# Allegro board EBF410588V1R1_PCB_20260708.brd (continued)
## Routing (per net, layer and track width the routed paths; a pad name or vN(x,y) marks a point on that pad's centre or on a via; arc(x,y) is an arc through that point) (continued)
VBUS5V0_TYPEC: length 36.8
  TOP w0.254: v1(26.56,81.61) J10.A9 ; v1(26.36,86.39) 26.8,85.96 J10.B4 ; J10.A4 29.06,81.73 v1(29.16,81.64) ; v1(29.8,86.39) 29.3,85.89 J10.B9
  TOP w0.305: v1(41.12,66.5) 42.88,68.25 42.88,69.14 42.24,69.77 42.24,83.64 v1(41.25,84.63)
  TOP w0.381: v1(26.57,80.75) 26.56,80.75 v1(26.56,81.61) ; v1(29.8,86.39) v1(29.8,87.39) ; v1(26.36,86.39) v1(26.36,87.39) ; v1(29.16,81.64) v1(29.74,81.05)
  BOTTOM w0.254: U11.2 40.97,66.34 v1(41.12,66.5)
  BOTTOM w0.508: 26.64,81.54 26.64,80.82 v1(26.57,80.75) 26.57,80.47 26.79,80.25 C103.1 ; 26.64,81.54 v1(26.56,81.61) ; 26.64,81.54 26.74,81.43 28.96,81.43 v1(29.16,81.64) v1(29.74,81.05)
VCC3V3_RTC_S5: length 24
  BOTTOM w0.254: R241.1 21.97,46.35 24.18,44.15 32.87,44.15 U6.2
  BOTTOM w0.381: D9.2 38.02,49.5 38.02,48.44 37.47,47.89 C31.1 36.89,47.43 U6.2
VCC5V0_SYS_S5: length 203.9
  ART04 w0.254: v1(3.38,50.11) 3.35,50.11 2.46,49.22 2.46,46.23 2.82,45.87 2.82,9.17 3.35,8.64 7.65,8.64 8.15,8.13 8.15,1.83 8.66,1.32 118.8,1.32 119.1,1.02 135.46,1.02 136.22,1.78 136.91,1.78 v1(137.53,2.4)
  BOTTOM w0.254: v1(60.05,39.42) 60.05,39.66 R198.2 ; R6.2 C11.2 12.62,60.71 13.13,60.2 13.13,55.65 12.01,54.53 ; R4.1 v1(137.53,2.4) ; v1(3.38,50.11) 4.27,51 9.96,51 11.67,52.71 v1(11.67,52.72)
  vias: v1(11.67,53.72) v1(12.67,53.72) v1(12.67,52.72) v1(13.67,53.72) v1(13.67,52.72) v1(34.52,47.37) v1(51.12,17.51) v1(51.12,16.51) v1(52.12,17.51) v1(52.12,16.51) v1(53.12,17.51) v1(53.12,16.51)
VCC5V0_USB20_HOST: length 16.7
  ART04 w0.508: J11.10 120.19,77.18 ; J11.10 119.46,77.91 ; J11.10 118.73,77.18 ; J11.10 119.46,76.45 ; J12.7 138.33,78.5 ; J12.7 137.36,79.48 ; J12.7 136.38,78.5 ; J12.7 137.36,77.52
  BOTTOM w1.016: 137.57,85.29 137.57,78.71 J12.7 J12.1
VCC5V0_USB30_HOST: length 5.1
  BOTTOM w0.762: J11.1 119.46,85.44
VCC_1V8_S3: length 124.6
  TOP w0.254: 37.71,49.67 v1(30.87,49.67) 29.68,49.67 28.35,48.34 v1(25.83,48.34)
  TOP w0.381: v1(39.67,48.83) 38.55,48.83 37.71,49.67 37.73,49.67 38.25,50.19 38.25,54.25 39.56,55.56 v1(42.59,55.56)
  ART03 w0.381: v1(42.59,55.56) 42.72,55.69 42.72,59 41.99,59.74 41.99,66.45 42.57,67.03 44.07,67.03 44.48,67.44 45.9,67.44 47.99,65.34 53.24,65.34 v1(53.69,64.9) 54.51,65.72 54.51,66.67 56.11,68.28 69.93,68.28 72.14,66.07 72.14,64.2 v1(72.31,64.02)
  BOTTOM w0.254: R159.1 76.19,63 74.55,64.64 72.93,64.64 v1(72.31,64.02) ; v1(53.69,64.9) 53.94,64.64 56.02,64.64 R158.1 ; v1(25.83,48.34) 26.38,48.89 R156.1
  BOTTOM w0.508: D58.2 59.09,8.73 59.82,8 64.39,8 65,7.39 65,5.28 65.43,4.85 65.43,2.69 65.94,2.18 80.26,2.18 80.77,2.69 92.7,2.69 J30.1
  vias: v1(56.47,13.87) v1(56.47,12.87)
VCC_3V3_S0: length 105.1
  ART03 w0.508: v1(128.1,17.7) 126.47,16.07 126.47,13.92 125.6,13.06 113.84,13.06 109.8,9.02 109.8,7.01 108.61,5.82 98.63,5.82 94.26,1.45 62.53,1.45 61.37,2.62 61.37,6.5 58.32,9.55 58.32,10.77 57.23,11.86 53.61,11.86 53.1,12.37 53.1,15.49 v1(54.12,16.51) v1(54.12,17.51)
  BOTTOM w0.305: J4.4 132.49,18.51 C21.1 132.45,18.48 131.88,17.91 130.42,17.91 C20.1 129.79,18.48 129.24,17.93 128.33,17.93 v1(128.1,17.7)
  vias: v1(55.12,17.51) v1(55.12,16.51)
VCC_RTC: length 14.6
  BOTTOM w0.254: D9.3 34.12,53.45 33.66,53.92 30.23,53.92 29.49,53.18 29.49,50.3 29.84,49.94 R157.1 R32.1
  BOTTOM w0.305: C26.1 32.42,51.35 U5.8
  BOTTOM w0.381: D9.3 33.5,52.32 33,51.82 C26.1
VCCA1V8_PLDO2_S0: length 19.7
  TOP w0.254: CN4.21 56.32,15.79 56.12,15.99 v1(56.12,16.51)
  BOTTOM w0.254: v1(39.67,49.83) 40.52,50.67 42.55,50.67 44.55,52.68 55.1,52.68 R15.1
VDD_3V3: length 285.6
  TOP w0.203: U7.28 61.91,59.86 62.1,59.66 62.31,59.87 U7.29 ; U8.28 80.32,59.84 80.51,59.65 80.72,59.87 U8.29
  TOP w0.254: R82.2 R91.1 L9.1 v1(44.74,68.95) ; v1(49.17,69.8) 49.47,69.8 R87.1 ; U28.5 v1(3.44,78.48) ; C33.1 64.02,58.31 63.09,59.23 62.33,59.23 62.1,59.46 62.1,59.66 ; R21.1 v1(140.59,6.78) ; v1(35.56,83.54) 36.25,82.85 36.25,70.33 35.88,69.97 v1(35.88,68.33) ; v1(78.23,54.13) R58.1 R57.1 ; U29.5 v1(7.31,68.09) ; R142.1 v1(100.76,54.86) ; R35.1 57.78,54.1 58.29,53.59 59.31,53.59 59.82,54.1 R34.1 R33.1 v1(60.83,54.13) ; v1(71.25,22.86) 71.25,20.22 v1(74.4,17.07) v1(74.4,15.95) 74.4,13.87 v1(74.37,13.84) ; R141.1 v1(104.19,54.86) ; 80.51,59.65 80.51,59.42 80.7,59.23 81.49,59.23 C51.1
  TOP w0.305: v1(81.28,54.13) R59.1 81.36,54.87 82.37,55.88 C49.1 C50.1 C51.1
  TOP w0.381: v1(12.7,16.1) C196.1 14.04,16.9 14.35,16.59 U35.5 ; R22.1 v1(135.53,8.5) ; L16.1 v1(38.35,10.63) ; U34.5 21.72,16.59 21.4,16.9 C189.1 v1(19.94,16.1) ; L15.2 12.99,32.03 v1(13.44,32.03) ; v1(35.88,68.33) 36.39,67.82 40.44,67.82 v1(41.12,68.5) ; R127.1 v1(131.32,54.15)
  TOP w0.508: C34.1 v1(64.02,56.58) C35.1 C33.1 ; v1(54.9,60.97) 54.77,60.84 L8.1
  ART03 w0.254: v1(7.31,68.09) 7.31,65.71 7.82,65.2 16.28,65.2 v1(16.81,65.74) ; v1(100.76,54.86) v1(104.19,54.86) 106.45,54.86 108.31,56.73 v1(108.31,66.79)
  ART03 w0.508: v1(19.94,16.1) 19.43,15.6 15.24,15.6 14.73,16.1 v1(12.7,16.1)
  ART04 w0.254: v1(84.26,60.58) 86.26,60.58 87.05,61.37 89.28,61.37
  ART04 w0.508: 29.87,30.2 30.42,30.75 v1(30.91,30.75) ; 144.73,43.01 J32.17 ; J32.17 143.75,43.99 ; J32.17 144.73,44.97
  BOTTOM w0.254: v1(16.81,65.74) 17.26,65.29 R3.1 ; R145.1 137.45,6.88 140.49,6.88 v1(140.59,6.78) 140.96,6.41 R144.1 ; U11.13 39.19,68.02 38.94,68.28 ; v1(3.44,78.48) 3.44,78.49 C176.1 5.34,77.46 6.34,76.46 C177.1 7.04,67.82 v1(7.31,68.09) ; 38.94,68.28 38.94,68.55 38.73,68.76 37.08,68.76 36.83,68.5 36.83,67.82 36.58,67.56 C91.1 ; 38.94,68.28 38.69,68.03 U11.12 ; L5.1 v1(57.42,68.87) ; v1(74.37,13.84) R160.1 R162.1 ; R109.1 41.92,66.4 C92.1 41.34,65.84 U11.3 ; R189.1 96.16,18.16 96.75,17.58 102.95,17.58 105.16,15.36 v1(105.16,11.12) ; R189.1 R190.1 ; R189.1 96.13,18.15 95.5,17.53 94.11,17.53 93.6,17.02 93.6,13.59 94.1,13.09 R163.1 R188.1 ; R77.1 77.21,62.99 R72.1 R71.1 78.22,59.95 R70.1 83.63,59.95 v1(84.26,60.58) 85.5,60.58 85.95,61.04 85.95,61.96 R150.1 ; R236.1 v1(74.4,17.07) ; v1(30.91,30.75) 30.17,31.49 30.17,32.43 30.53,32.79 32.44,32.79 36.65,37.01 49.08,37.01 R240.1 R239.1 ; R238.1 R237.1 71.64,23.25 v1(71.25,22.86) ; v1(81.28,54.13) 81.42,54.26 R103.1 ; v1(107.31,66.79) 106.56,66.03 R146.1 104.19,64.81 Q7.1 ; R97.2 v1(35.56,83.54) ; R235.1 v1(74.4,15.95) ; R12.1 v1(140.96,2.64) ; v1(89.59,65.13) 89.9,64.81 Q6.1 90.61,64.2 90.32,63.91 89.64,63.91 89.38,63.65 89.38,63.1 R139.1 ; v1(65.85,60.58) 65.22,59.95 R46.1 59.67,59.95 R47.1 R48.1 58.67,61.98 R53.1 ; U25.5 v1(124.14,16.65)
  BOTTOM w0.305: R136.1 81.41,47.23 v1(81.37,47.27) ; L7.1 v1(75.83,68.87)
  BOTTOM w0.381: v1(32.51,9.63) 32.53,9.63 33.53,10.63 L17.1 ; v1(44.74,68.95) 44.86,68.83 44.86,67.13 44.35,66.62 44.35,65 44.09,64.74 43.37,64.74 42.92,65.18 R109.1 ; C91.1 v1(35.88,68.33) 35.88,69.07 35.43,69.52 33.6,69.52 32.49,70.64 18.11,70.64 17.4,69.93 17.4,66.32 v1(16.81,65.74)
  vias: v1(53.9,10.18) v1(53.9,9.18) v1(54.9,10.18) v1(54.9,9.18) v1(68.55,8.97) v1(69.6,8.97) v1(70.6,8.97) v1(70.6,7.97) v1(107.31,67.79) v1(108.31,67.79) v1(114.92,42.27) v1(115.92,42.27) v1(123.14,17.65) v1(123.14,16.65) v1(129.32,68.04) v1(129.32,67.04) v1(130.32,68.04) v1(130.32,67.04)
VDD_5V: length 39.8
  TOP w0.254: C153.1 11.13,29.72 v1(11.14,29.71) ; R10.1 49.5,54.51 v1(49.96,54.51) ; Q1.2 49.59,55.68 v1(49.96,55.31) ; R126.1 v1(129.29,57.59) ; C151.1 11.13,13.84 v1(11.14,13.84)
  TOP w0.381: U34.3 22.99,21.84 C190.1 v1(22.33,21.97) ; v1(14.96,21.97) C197.1 15.62,21.84 U35.3
  ART04 w0.508: J32.4 148.25,61.77 ; J32.4 147.27,60.79 ; J32.4 147.27,62.75 ; J32.4 146.29,61.77 ; 146.29,64.31 J32.2 ; J32.2 147.27,65.29 ; J32.2 148.25,64.31 ; J32.2 147.27,63.33
  BOTTOM w0.254: R147.1 100.97,65.54 103.27,65.54 v1(103.54,65.82) ; C8.1 17.26,55.06 19.1,56.9 19.1,61.21 18.59,61.72 C2.2 R1.2 ; R140.1 91.32,65.66 88.16,65.66 Q10.1 ; C155.1 v1(11.13,25.78) ; U24.5 v1(117.54,16.65)
  vias: v1(9.93,47.09) v1(10.74,47.09) v1(11.14,30.71) v1(11.13,24.78) v1(11.14,12.84) v1(17.67,53.72) v1(17.67,52.72) v1(18.67,53.72) v1(18.67,52.72) v1(19.67,53.72) v1(19.67,52.72) v1(27.97,59.64) v1(27.97,58.64) v1(33.66,79.12) v1(33.66,78.12) v1(34.65,79.12) v1(34.65,78.12) v1(73.24,8.97) v1(74.3,8.97) v1(75.29,8.97) v1(75.29,7.97) v1(94.31,66.3) v1(94.31,65.3) v1(116.3,88.1) v1(116.3,87.1) v1(116.54,17.65) v1(116.54,16.65) v1(117.53,87.1) v1(132.68,88.1) v1(132.68,87.1) v1(133.91,87.1)
BAT_RTC: length 6.9
  BOTTOM w0.381: D9.1 36.89,53.28 C24.1 38.01,53.5 D10.2 38.73,54.86 39.49,55.62 J5.1
BM8563_INT: length 9.9
  BOTTOM w0.152: R157.2 R32.2 28.83,47.95 D18.1 ; Q3.1 25.43,49.53 27.25,49.53 D18.1 ; D18.1 28.17,49.58 28.17,52.37 27.89,52.65 U5.3
BOOT_SARADC_IN0: length 125.4
  TOP w0.152: v1(58.12,17.51) 57.61,16.99 57.61,16.31 57.92,15.99 CN4.29 ; v1(57.67,26.99) 58.65,26.01 100.51,26.01 109.58,35.08 109.58,46.81 111.61,48.84 122.48,48.84 122.86,49.23 129.11,49.23 132.55,52.67 132.55,66.59 v1(133.05,67.08)
  ART03 w0.152: v1(58.12,17.51) 58.12,26.53 v1(57.67,26.99)
  BOTTOM w0.152: v1(133.05,67.08) 133.05,70.17 R27.2
CAM0_PWDN: length 125.9
  TOP w0.152: J14.15 5.33,19.35 4.98,18.99 4.98,16.21 3.73,14.96 3.73,13.24 2.59,12.09 2.59,9.6 2.79,9.4 6.43,9.4 8,7.82 8,4.92 9.29,3.64 39.25,3.64 40.54,4.93 40.54,9.46 v1(40.37,9.63) ; CN2.7 53.52,45.04 52.61,44.13 51.38,44.13 49.68,45.82 49.68,49.05 47.53,51.21 42.98,51.21 42.44,50.67 41.21,50.67 v1(40.18,51.7)
  ART03 w0.152: v1(40.37,9.63) 40.37,9.64 40.85,10.12 40.85,11.12 40.18,11.79 40.18,16.05 40.59,16.46 40.59,19.05 44.42,22.89 44.42,41.05 40.18,45.29 v1(40.18,51.7)
CAM0_RSTN: length 129.8
  TOP w0.152: v1(41.37,9.63) 41.02,9.28 41.02,4.6 39.58,3.16 9.06,3.16 7.52,4.7 7.52,7.57 6.17,8.92 2.57,8.92 2.11,9.37 2.11,12.29 3.25,13.44 3.25,15.16 4.45,16.36 4.45,19.18 5.04,19.77 5.04,22.54 5.35,22.85 J14.22 ; CN2.5 53.12,45.29 52.46,44.63 51.59,44.63 50.22,46 50.22,49.2 47.69,51.72 42.81,51.72 42.24,51.16 41.72,51.16 v1(41.18,51.7)
  ART03 w0.152: v1(41.37,9.63) 41.37,11.31 40.67,12.01 40.67,15.57 41.54,16.44 41.54,19.09 45.36,22.91 45.36,40.79 40.67,45.49 40.67,51.18 v1(41.18,51.7)
CAM1_PWDN: length 121.6
  TOP w0.152: v1(3.37,32.55) 3.86,33.04 3.86,33.4 4.83,34.37 4.83,35.1 5.38,35.66 5.38,38.02 5.91,38.55 J15.15 ; v1(90.72,18.51) 90.72,16.15 89.92,15.35 CN5.71
  BOTTOM w0.152: v1(3.37,32.55) 2.62,31.79 2.62,28.7 3.15,28.17 8.79,28.17 9.35,28.73 12.34,28.73 12.95,29.34 15.8,29.34 16.21,29.74 30.68,29.74 31.37,29.06 41.2,29.06 42.27,30.12 42.27,32.26 43.61,33.6 62.2,33.6 65.07,30.73 89.61,30.73 91.34,29.01 91.34,19.12 v1(90.72,18.51)
CAM1_RSTN: length 125.5
  TOP w0.152: CN5.69 89.52,15.48 90.22,16.18 90.22,19 v1(90.72,19.51) ; v1(3.37,33.55) 3.37,33.62 4.32,34.57 4.32,35.31 4.88,35.86 4.88,41.76 5.17,42.05 J15.22
  BOTTOM w0.152: v1(90.72,19.51) 90.72,28.68 89.18,30.23 64.9,30.23 62.03,33.1 43.94,33.1 42.8,31.95 42.8,29.84 41.5,28.55 30.94,28.55 30.51,28.98 28.98,28.98 28.52,28.52 15.98,28.52 15.67,28.83 13.26,28.83 12.65,28.22 9.65,28.22 9.12,27.69 2.9,27.69 2.13,28.45 2.13,32.31 v1(3.37,33.55)
CAM2_PWDN: length 121.2
  TOP w0.152: v1(92.72,19.51) 91.54,19.51 91.24,19.2 91.24,16.15 90.32,15.24 CN5.73
  ART03 w0.152: v1(31.42,22.96) 31.42,31.24 v1(30.91,31.75)
  BOTTOM w0.152: v1(92.72,19.51) 92.37,19.86 92.37,29.78 90.58,31.57 65.57,31.57 62.57,34.57 42.75,34.57 39.01,30.83 35.1,30.83 34.39,30.12 32.66,30.12 32.41,30.38 32.41,31.05 32.19,31.27 31.39,31.27 v1(30.91,31.75) ; J16.15 7.63,16.85 8.31,17.53 8.31,19.13 12.22,23.04 22.02,23.04 22.81,22.25 24.31,22.25 25.03,22.97 31.41,22.97 v1(31.42,22.96)
CAM2_RSTN: length 94.8
  TOP w0.152: CN2.3 52.72,45.46 52.4,45.14 51.79,45.14 50.8,46.13 50.8,49.35 47.95,52.2 42.6,52.2 v1(42.14,51.74)
  ART03 w0.152: v1(42.31,19.05) 45.85,22.58 45.85,41.07 41.27,45.64 41.27,50.85 42.14,51.71 v1(42.14,51.74)
  BOTTOM w0.152: J16.22 9.33,13.35 10.49,12.19 11.48,12.19 12.04,12.75 14.66,12.75 15.39,13.49 15.39,17.14 17.42,19.18 25.76,19.18 26.7,18.24 38.71,18.24 39.52,19.05 v1(42.31,19.05)
CAM3_PWDN: length 146.7
  TOP w0.152: J18.15 4.96,57.37 4.72,57.61 4.72,59.56 4.42,59.87 v1(2.5,59.87) ; v1(89.72,19.51) 89.2,18.99 89.2,16.21 88.72,15.73 CN5.65
  BOTTOM w0.152: v1(2.5,59.87) 1.65,59.02 1.65,48.79 1.17,48.31 1.17,27.94 2.49,26.62 9.58,26.62 10.19,27.23 15.65,27.23 15.95,27.53 42.19,27.53 43.87,29.21 43.87,31.45 44.53,32.11 61.59,32.11 64.44,29.26 88.26,29.26 89.72,27.8 v1(89.72,19.51)
CAM3_RSTN: length 146.2
  TOP w0.152: J18.22 v1(2.5,60.87) ; v1(89.72,18.51) 89.72,16.19 89.12,15.59 CN5.67
  BOTTOM w0.152: v1(2.5,60.87) 3.02,60.34 3.02,59.51 2.13,58.62 2.13,48.44 1.65,47.96 1.65,28.19 2.74,27.1 9.3,27.1 9.91,27.71 15.45,27.71 15.78,28.04 28.73,28.04 29.18,28.5 30,28.5 30.45,28.04 41.83,28.04 43.31,29.51 43.31,31.65 44.25,32.59 61.82,32.59 64.67,29.74 88.7,29.74 90.22,28.22 90.22,18.95 89.78,18.51 v1(89.72,18.51)
CAM4_PWDN: length 73.7
  TOP w0.152: CN2.9 53.92,44.88 52.63,43.59 41.68,43.59 37.97,47.29 35.64,47.29 34.75,48.18 30.15,48.18 28.85,46.89 27.05,46.89 25.73,45.57 23.44,45.57 21.64,47.37 18.26,47.37 16.59,49.05 15.76,49.05 v1(15.24,49.56)
  BOTTOM w0.152: J17.15 3.04,36.05 2.62,36.47 2.62,47.42 4.76,49.56 v1(15.24,49.56)
CAM4_RSTN: length 78
  TOP w0.152: CN2.11 54.32,44.72 52.7,43.1 41.43,43.1 37.85,46.69 34.26,46.69 33.27,47.68 30.4,47.68 29.08,46.35 27.83,46.35 v1(26.69,45.21) ; v1(25.27,46.14) 24.65,46.76 23.06,46.76 21.97,47.85 18.73,47.85 17.02,49.56 v1(16.24,49.56)
  BOTTOM w0.152: v1(25.27,46.14) 25.76,46.14 v1(26.69,45.21) ; J17.22 5.32,32.55 2.13,35.74 2.13,47.7 4.57,50.14 15.67,50.14 v1(16.24,49.56)
CAN0_H: length 15.1
  TOP w0.203: U34.7 24.26,14.07 23.78,13.6 23.78,13.2 23.33,12.75 22.33,12.75 22.08,12.5 22.08,12.08 R205.1 D57.1 23.38,11.23 23.17,11.02 22.23,11.02 22.02,10.82 22.02,9.99 19.74,7.7 19.74,6.35 20.04,6.05 J29.1
CAN0_L: length 15.4
  TOP w0.203: U34.6 22.99,14.07 23.43,13.63 23.43,13.35 23.19,13.11 22.18,13.11 21.72,12.64 21.72,12.19 R205.2 D47.1 20.31,11.28 20.52,11.07 21.41,11.07 21.67,10.82 21.67,10.13 19.38,7.85 19.38,6.35 19.08,6.05 J29.2
CAN0_RX_M2: length 76.4
  TOP w0.152: v1(86.72,11.18) 87.12,11.58 CN5.58 ; U34.4 21.72,18.82 22.91,17.63 28.37,17.63 28.77,17.22 40.34,17.22 41.81,18.69 41.81,21.22 v1(42.56,21.97)
  BOTTOM w0.152: v1(42.56,21.97) 43.17,21.36 62.81,21.36 66.15,18.02 78.27,18.02 81.86,14.43 83.69,14.43 84.74,13.38 84.74,12.31 85.88,11.18 v1(86.72,11.18)
CAN0_TX_M2: length 74.7
  TOP w0.152: CN5.60 87.52,12.72 v1(87.22,13.02) ; U34.1 25.53,18.31 25.83,18.01 28.52,18.01 28.93,17.6 40.08,17.6 41.35,18.87 41.35,21.77 v1(41.56,21.97)
  BOTTOM w0.152: v1(41.56,21.97) 42.04,22.45 43.05,22.45 43.74,21.77 63.2,21.77 66.29,18.67 73.91,18.67 74.24,19 77.19,19 77.93,19.74 79.6,19.74 80.54,18.8 80.54,16.43 82.07,14.91 83.77,14.91 85.17,13.51 86.73,13.51 v1(87.22,13.02)
CAN1_H: length 15.6
  TOP w0.203: J29.3 12.44,6.05 12.09,6.4 12.09,7.62 12.75,8.28 14.19,8.28 15.42,9.5 15.42,10.85 15.67,11.1 16.48,11.1 16.77,11.39 D30.1 R206.1 15.44,12.11 15.44,12.65 15.6,12.8 15.94,12.8 16.35,13.21 16.35,13.76 16.89,14.3 U35.7
CAN1_L: length 15.9
  TOP w0.203: U35.6 15.62,14.1 16,13.72 16,13.36 15.79,13.16 15.44,13.16 15.09,12.8 15.09,12.16 R206.2 D25.1 13.71,11.36 13.94,11.13 14.78,11.13 15.06,10.85 15.06,9.65 14.05,8.64 12.6,8.64 11.73,7.77 11.73,6.3 11.48,6.05 J29.4
CAN1_RX_M3: length 59.5
  TOP w0.152: CN4.62 64.32,11.38 v1(64.12,11.18) ; U35.4 14.35,18.49 14.96,17.88 18.29,17.88 18.87,18.47 20.9,18.47 22.48,16.89 28.06,16.89 28.47,16.48 39.57,16.48 39.98,16.08 40.6,16.08 v1(41.13,16.61)
  BOTTOM w0.152: v1(41.13,16.61) 41.39,16.87 44.95,16.87 46.14,18.06 60.81,18.06 62.36,16.51 62.36,15.47 63.12,14.71 63.12,12.18 v1(64.12,11.18)
CAN1_TX_M3: length 53.2
  TOP w0.152: v1(63.62,12.87) 63.92,12.57 CN4.60 ; U35.1 18.16,19.05 18.39,18.82 21.08,18.82 22.66,17.25 28.21,17.25 28.61,16.84 39.9,16.84 v1(40.13,16.61)
  BOTTOM w0.152: v1(40.13,16.61) 40.82,17.3 44.77,17.3 45.94,18.47 60.91,18.47 63.62,15.75 v1(63.62,12.87)
CTP_INT: length 157.6
  TOP w0.152: v1(139.83,19.56) 139.83,18.87 141.15,17.55 J13.11 145.57,17.55 148.13,14.99 148.13,8.84 147.73,8.43 143.81,8.43 141.5,6.12 141.5,3.96 141.2,3.65 140.23,3.65 v1(139.75,4.14) ; v1(51.67,27.99) 51.67,28.47 52.28,29.08 54,29.08 56.14,31.23 95.67,31.23 96.5,30.4 v1(96.5,30.03) ; v1(53.92,51.79) 54.41,51.3 54.41,50.47 54.72,50.15 CN2.14
  ART03 w0.152: v1(96.5,30.03) 96.5,24.89 97.66,23.72 122.63,23.72 123.7,22.66 129.67,22.66 132.19,20.13 136.33,20.13 137.64,18.82 139.09,18.82 v1(139.83,19.56) ; v1(51.67,27.99) 51.28,28.37 51.28,47.7 53.34,49.76 53.34,51.23 53.89,51.79 v1(53.92,51.79)
  BOTTOM w0.152: R144.2 139.96,4.35 v1(139.75,4.14)
CTP_RST: length 161.4
  TOP w0.152: v1(94.5,30.03) 94.48,30.05 57.1,30.05 54.53,27.48 53.17,27.48 v1(52.67,27.99) ; CN2.16 55.12,50.34 54.92,50.54 v1(54.92,50.79) ; v1(142.39,18.05) J13.12 145.91,18.05 148.62,15.34 148.62,8.64 147.93,7.95 144.07,7.95 141.99,5.87 141.99,3.48 141.68,3.17 138.9,3.17 v1(137.94,4.14)
  ART03 w0.152: v1(94.5,30.03) 94.5,29.91 94.01,29.42 94.01,21.68 97.54,18.16 109.47,18.16 110.24,18.92 123.72,18.92 124.21,19.41 129.72,19.41 131.34,17.78 135.64,17.78 137.01,16.41 140.75,16.41 141.11,16.76 142.06,16.76 142.39,17.09 v1(142.39,18.05) ; v1(52.67,27.99) 52.67,29.05 52.37,29.34 52.37,46.3 52.76,46.69 52.76,47.47 54.92,49.64 v1(54.92,50.79)
  BOTTOM w0.152: R145.2 137.53,4.54 v1(137.94,4.14)
DP_TX_AUXN: length 116.6
  TOP w0.109: v1(33.91,31.62) 34.12,31.4 arc(34.23,31.33) 34.35,31.31 35.73,31.31 arc(35.98,31.26) 36.19,31.12 36.46,30.85 arc(36.53,30.8) 36.62,30.78 39.97,30.78 arc(40.45,30.88) 40.85,31.15 41.69,31.99 arc(42.19,32.32) 42.78,32.44 76.21,32.44 arc(76.96,32.58) 77.58,33 84.63,40.05 arc(85.05,40.68) 85.2,41.42 85.2,45.3 85.12,45.38 CN3.47
  ART03 w0.089: v1(33.91,31.62) 34.13,31.39 arc(34.23,31.33) 34.33,31.31 34.39,31.31 arc(34.46,31.32) 34.52,31.36 34.56,31.4 arc(34.62,31.49) 34.65,31.6 34.65,37.74 arc(34.62,37.89) 34.53,38.02 32.78,39.77 arc(32.39,40.35) 32.26,41.03 32.26,49.42 arc(32.23,49.58) 32.13,49.71 31.71,50.14 arc(31.51,50.43) 31.45,50.77 31.45,57.7 arc(31.42,57.85) 31.33,57.98 28.9,60.41 arc(28.71,60.7) 28.64,61.04 28.64,67.49 arc(28.61,67.64) 28.52,67.77 26.14,70.15 arc(26.01,70.24) 25.86,70.27 25.55,70.27 arc(25.21,70.34) 24.92,70.53 20.47,74.98 arc(20.25,75.32) 20.17,75.71 20.17,75.74 arc(20.28,76.02) 20.56,76.16 20.56,76.16 arc(20.72,76.21) 20.86,76.3 v1(21.06,76.5)
  BOTTOM w0.109: C106.2 22.98,76.72 arc(23.08,76.57) 23.12,76.4 23.12,76.3 arc(23.08,76.22) 23.01,76.19 21.5,76.19 arc(21.37,76.21) 21.27,76.28 v1(21.06,76.5)
DP_TX_AUXP: length 117.7
  TOP w0.109: CN3.49 85.52,45.38 85.45,45.3 85.45,41.42 arc(85.28,40.58) 84.81,39.87 77.76,32.83 arc(77.05,32.35) 76.21,32.19 42.78,32.19 arc(42.28,32.09) 41.86,31.81 41.03,30.97 arc(40.54,30.65) 39.97,30.54 36.62,30.54 arc(36.44,30.57) 36.29,30.67 36.02,30.94 arc(35.89,31.03) 35.73,31.06 34.24,31.06 arc(34.12,31.04) 34.02,30.97 33.91,30.86 v1(33.91,30.75)
  ART03 w0.089: v1(33.91,30.75) 33.91,30.94 34.06,31.09 34.11,31.09 34.14,31.12 34.39,31.12 arc(34.54,31.15) 34.66,31.23 34.7,31.27 arc(34.8,31.42) 34.84,31.6 34.84,37.74 arc(34.79,37.97) 34.66,38.16 32.91,39.91 arc(32.57,40.42) 32.45,41.03 32.45,49.42 arc(32.4,49.65) 32.27,49.85 31.84,50.28 arc(31.69,50.5) 31.64,50.77 31.64,57.7 arc(31.59,57.92) 31.46,58.11 29.03,60.54 arc(28.88,60.77) 28.83,61.04 28.83,67.49 arc(28.78,67.71) 28.66,67.9 26.27,70.29 arc(26.08,70.42) 25.86,70.46 25.55,70.46 arc(25.28,70.51) 25.06,70.66 20.6,75.12 arc(20.42,75.39) 20.36,75.71 20.36,75.74 arc(20.42,75.89) 20.57,75.97 arc(20.58,75.97) 20.59,75.97 20.9,75.97 arc(21.01,75.92) 21.06,75.81 v1(21.06,75.63)
  BOTTOM w0.109: C105.2 23.55,76.77 arc(23.41,76.57) 23.37,76.33 23.37,76.3 arc(23.26,76.05) 23.01,75.94 21.5,75.94 arc(21.37,75.92) 21.27,75.85 v1(21.06,75.63)
DSI_VDD3V3:
  vias: v1(140.4,13.89) v1(141.4,13.89) v1(142.4,13.89)
DSI_VDD5V:
  vias: v1(142.4,11.97) v1(142.4,10.97) v1(143.4,11.97) v1(143.4,10.97)
EARPHONE_CTL: length 72.4
  TOP w0.152: CN3.78 91.12,49.49 91.34,49.71 91.72,49.71 92.52,50.51 v1(92.52,50.79)
  ART03 w0.152: v1(43.18,71.25) 43.74,71.81 49.86,71.81 50.44,71.22 88.9,71.22 90.2,69.93 90.2,66.24 90.6,65.84 90.6,61.95 91.67,60.88 91.67,57.99 91.52,57.84 91.52,56.44 93.04,54.91 93.04,51.3 v1(92.52,50.79)
  BOTTOM w0.152: R95.2 v1(43.18,71.25)
ETH0_MCLK_M0: length 56.7
  TOP w0.102: CN5.17 79.12,17.83 79.3,18.01 79.3,19.28 78.61,19.96 77.44,19.96 77.09,20.32 75.91,20.32 v1(75.72,20.51) ; R49.1 v1(68.78,60.83)
  ART03 w0.097: v1(75.72,20.51) 76.22,21.01 78.65,21.01 78.92,21.28 78.92,35.67 73.58,41 73.58,53.53 72.36,54.76 72.36,56.36 69.27,59.45 69.27,60.35 v1(68.78,60.83)
ETH0_MDC_M0: length 97.9
  TOP w0.152: CN5.48 85.12,12.92 v1(85.22,13.02) ; U7.13 56.02,63.86 v1(55.91,63.98)
  ART03 w0.152: v1(55.91,63.98) 55.35,63.98 53.49,62.13 53.49,57.18 55.3,55.37 55.3,54 56.54,52.76 62.79,52.76 63.45,52.1 63.45,50.5 63.25,50.29 62.66,50.29 61.82,49.45 61.82,47.98 62.38,47.42 62.38,42.67 62.99,42.06 62.99,33.2 65.79,30.4 65.79,20.7 70.1,16.38 70.1,14.48 70.56,14.02 70.56,11.35 71.04,10.87 71.04,6.86 71.5,6.4 75.9,6.4 76.12,6.17 83.26,6.17 85.22,8.13 v1(85.22,13.02)
  BOTTOM w0.152: v1(55.91,63.98) 56.41,63.47 56.41,62.69 57.12,61.98 R48.2
ETH0_MDIO_M0: length 94.2
  TOP w0.152: U7.14 56.39,63.47 v1(55.9,62.97) ; CN5.46 v1(84.72,11.18)
  ART03 w0.152: v1(84.72,11.18) 84.72,8.37 82.91,6.55 76.58,6.55 76.17,6.96 71.91,6.96 71.6,7.26 71.6,11.18 71.13,11.65 71.13,14.36 70.66,14.83 70.66,16.54 66.37,20.83 66.37,30.61 64.11,32.87 64.11,42.16 63.35,42.93 63.35,47.45 63.04,47.75 62.59,47.75 62.18,48.16 62.18,49.35 62.74,49.91 63.92,49.91 64.33,50.32 64.33,52.18 63.32,53.19 56.85,53.19 55.83,54.2 55.83,55.52 54,57.35 54,61.95 55.02,62.97 v1(55.9,62.97)
  BOTTOM w0.152: R47.2 57.61,60.96 55.9,62.67 v1(55.9,62.97)
ETH0_RSTN: length 100.7
  TOP w0.152: v1(86.22,13.02) 85.97,13.02 85.52,12.57 CN5.50
  ART03 w0.152: v1(56.9,67.29) 55.45,65.84 55.45,64.92 52.4,61.87 52.4,57.51 54.72,55.19 54.72,53.89 56.34,52.27 62.12,52.27 62.43,51.96 62.43,50.65 61.21,49.43 61.21,46.23 61.52,45.93 61.52,41.96 62.43,41.05 62.43,32.89 65.3,30.02 65.3,20.47 69.57,16.21 69.57,14.1 70.03,13.64 70.03,5.92 70.43,5.51 83.51,5.51 86.22,8.22 v1(86.22,13.02)
  BOTTOM w0.152: D59.1 55.68,68.78 56.9,67.56 v1(56.9,67.29)
ETH0_RXCLK_M0: length 74.5
  TOP w0.102: R41.1 v1(62.87,56.58) R44.1 ; CN5.22 79.92,11.38 v1(79.72,11.18)
  ART03 w0.097: v1(79.72,11.18) 79.21,10.67 76.45,10.67 76.2,10.92 76.2,11.99 75.72,12.47 75.72,14.12 75.55,14.29 75.35,14.29 75.18,14.46 75.18,14.7 75.35,14.87 75.55,14.87 75.72,15.04 75.72,15.27 75.55,15.44 75.02,15.44 74.85,15.61 74.85,15.85 75.02,16.02 75.55,16.02 75.72,16.18 75.72,16.41 75.46,16.66 74.17,16.66 73.96,16.87 73.96,17.7 74.19,17.93 74.19,19.27 74.03,19.43 73.12,19.43 72.94,19.61 72.94,19.93 73.1,20.09 73.94,20.09 74.1,20.25 74.1,20.54 73.94,20.7 73.11,20.7 72.92,20.88 72.92,21.2 73.08,21.36 73.96,21.36 74.12,21.52 74.12,21.84 73.97,22 73.13,22 72.92,22.2 72.92,22.52 73.09,22.69 73.97,22.69 74.14,22.86 74.14,23.1 73.97,23.27 73.09,23.27 72.92,23.44 72.92,23.68 73.09,23.85 73.97,23.85 74.14,24.02 74.14,24.26 73.97,24.43 73.09,24.43 72.92,24.6 72.92,24.84 73.09,25.01 73.97,25.01 74.14,25.18 74.14,25.42 73.97,25.59 73.09,25.59 72.92,25.76 72.92,25.98 73.09,26.15 73.31,26.15 73.48,26.32 73.48,26.56 73.31,26.73 73.09,26.73 72.92,26.9 72.92,30.7 72.13,31.5 72.13,35.24 71.55,35.81 71.55,37.16 70.89,37.82 70.13,37.82 69.88,38.07 69.88,40.94 70.21,41.27 70.21,50.44 69.88,50.77 69.88,51.92 68.28,53.52 67.89,53.52 66.83,54.58 66.83,55.37 65.79,56.41 65.56,56.41 64.98,56.99 63.28,56.99 v1(62.87,56.58)
ETH0_RXCTL_M0: length 75.6
  TOP w0.102: R42.1 v1(61.85,56.58) R45.1 ; v1(80.22,13.02) 80.32,12.92 CN5.24
  ART03 w0.097: v1(61.85,56.58) 62.34,56.08 64.72,56.08 65.38,55.42 65.96,55.42 66.31,55.08 66.31,54.4 67.8,52.91 68.17,52.91 69.45,51.63 69.45,50.55 69.77,50.22 69.77,41.48 69.45,41.15 69.45,39.06 69.28,38.89 68.67,38.89 68.5,38.72 68.5,38.49 68.67,38.32 69.28,38.32 69.45,38.15 69.45,37.92 69.32,37.8 68.61,37.8 68.45,37.64 68.45,37.39 68.59,37.26 70.83,37.26 70.99,37.1 70.99,36.78 70.83,36.62 70.12,36.62 69.96,36.46 69.96,35.76 70.18,35.53 71.22,35.53 71.53,35.23 71.53,35.01 71.36,34.84 70.5,34.84 70.33,34.67 70.33,34.43 70.5,34.26 71.36,34.26 71.53,34.09 71.53,31.17 72.34,30.35 72.34,24.01 72.18,23.85 71.58,23.85 71.42,23.69 71.42,23.37 71.58,23.21 72.15,23.21 72.31,23.05 72.31,22.73 72.15,22.57 71.58,22.57 71.42,22.41 71.42,22.09 71.58,21.93 72.15,21.93 72.31,21.77 72.31,21.45 72.15,21.29 71.58,21.29 71.42,21.13 71.42,20.81 71.58,20.65 72.15,20.65 72.31,20.49 72.31,19.51 73.53,18.29 73.53,16.61 73.99,16.15 73.99,15.52 74.75,14.76 74.75,11.56 76.13,10.18 79.42,10.18 80.22,10.98 v1(80.22,13.02)
ETH0_RXD0_M0: length 74.8
  TOP w0.102: R37.1 v1(60.83,56.58) R33.2 ; CN5.26 v1(80.72,11.18)
  ART03 w0.097: v1(80.72,11.18) 80.72,10.82 79.59,9.69 76.01,9.69 74.12,11.58 74.12,13.41 73.74,13.79 73.74,15.09 73.05,15.77 73.05,18.11 70.82,20.35 70.82,24.34 70.98,24.5 71.57,24.5 71.73,24.66 71.73,24.98 71.57,25.14 70.98,25.14 70.82,25.3 70.82,25.62 70.98,25.78 71.57,25.78 71.73,25.94 71.73,26.26 71.57,26.42 70.98,26.42 70.82,26.58 70.82,26.9 70.98,27.06 71.57,27.06 71.73,27.22 71.73,27.54 71.57,27.7 70.98,27.7 70.82,27.86 70.82,28.18 70.98,28.34 71.57,28.34 71.73,28.5 71.73,28.82 71.57,28.98 70.98,28.98 70.82,29.14 70.82,29.46 70.98,29.62 71.57,29.62 71.73,29.78 71.73,30.1 71.57,30.26 70.98,30.26 70.82,30.42 70.82,30.71 70.66,30.87 70.06,30.87 69.9,31.03 69.9,31.35 70.06,31.51 70.66,31.51 70.82,31.67 70.82,31.99 70.66,32.15 70.06,32.15 69.9,32.31 69.9,32.63 70.06,32.79 70.66,32.79 70.82,32.95 70.82,33.27 70.66,33.43 70.06,33.43 69.9,33.59 69.9,33.91 67.92,35.89 67.92,39.19 68.12,39.4 68.78,39.4 68.99,39.6 68.99,41.61 69.35,41.97 69.35,50.03 69.01,50.37 69.01,51.35 68.01,52.35 67.54,52.35 64.31,55.58 61.84,55.58 v1(60.83,56.58)
ETH0_RXD1_M0: length 74.6
  TOP w0.102: v1(81.22,13.02) 81.12,12.92 CN5.28 ; R36.1 v1(59.82,56.58) R34.2
  ART03 w0.097: v1(81.22,13.02) 81.22,10.71 79.07,8.56 77.22,8.56 76.73,9.04 76.02,9.04 73.46,11.61 73.46,13.36 73.13,13.69 73.13,14.96 72.49,15.6 72.49,18.01 70.21,20.29 70.21,20.61 70.05,20.77 69.45,20.77 69.29,20.93 69.29,21.25 69.45,21.41 70.05,21.41 70.21,21.57 70.21,21.89 70.05,22.05 69.45,22.05 69.29,22.21 69.29,22.53 69.45,22.69 70.02,22.69 70.18,22.85 70.18,29.97 69.95,30.2 69.39,30.2 69.19,30.4 69.19,33.83 67.44,35.59 67.44,39.65 67.69,39.9 68.22,39.9 68.4,40.08 68.4,40.3 68.23,40.47 67.12,40.47 66.95,40.64 66.95,40.88 67.12,41.05 68.23,41.05 68.4,41.22 68.4,44.37 68.92,44.89 68.92,49.85 68.58,50.19 68.58,50.9 68.22,51.26 67.61,51.26 67.33,51.54 67.33,51.92 64.2,55.05 61.35,55.05 v1(59.82,56.58)
ETH0_RXD2_M0: length 75.1
  TOP w0.102: CN5.30 81.52,11.38 v1(81.72,11.18) ; R43.1 v1(58.8,56.58) R39.1
  ART03 w0.097: v1(58.8,56.58) 60.82,54.56 63.75,54.56 66.52,51.79 66.52,50.62 66.78,50.37 67.77,50.37 68.49,49.64 68.49,45.28 67.41,44.2 67.41,42.34 66.4,41.33 66.4,35.76 68.64,33.51 68.64,29.63 68.8,29.47 69.23,29.47 69.39,29.31 69.39,28.99 69.23,28.83 68.8,28.83 68.64,28.67 68.64,28.35 68.8,28.19 69.23,28.19 69.39,28.03 69.39,27.71 69.23,27.55 68.8,27.55 68.64,27.39 68.64,25.59 68.8,25.43 69.46,25.43 69.62,25.27 69.62,24.95 69.46,24.79 68.8,24.79 68.64,24.63 68.64,24.31 68.8,24.15 69.46,24.15 69.62,23.99 69.62,23.67 69.46,23.51 68.8,23.51 68.64,23.35 68.64,20.83 71.96,17.51 71.96,15.39 72.59,14.76 72.59,13.54 72.82,13.31 72.82,11.63 74.83,9.63 74.83,8.63 75.08,8.38 76.66,8.38 76.96,8.08 79.2,8.08 81.72,10.6 v1(81.72,11.18)
ETH0_RXD3_M0: length 74.8
  TOP w0.102: v1(82.22,13.02) 81.92,12.72 CN5.32 ; R40.1 v1(57.78,56.58) R35.2
  ART03 w0.097: v1(82.22,13.02) 82.22,9.98 79.5,7.26 76.81,7.26 76.5,7.57 75.13,7.57 73.81,8.89 73.81,9.98 72.29,11.51 72.29,13.18 72.09,13.39 72.09,14.5 71.42,15.16 71.42,17.42 67.74,21.11 67.74,33.53 65.79,35.48 65.79,41.53 66.5,42.24 66.5,44.27 66.9,44.68 67.23,44.68 68.07,45.51 68.07,49.36 67.59,49.83 66.24,49.83 65.35,50.72 65.35,52.07 63.71,53.72 60.65,53.72 v1(57.78,56.58)
ETH0_TXCLK_M0: length 72.8
  TOP w0.102: CN5.21 79.92,19.59 78.89,20.62 77.8,20.62 77.39,21.03 76.45,21.03 75.98,21.51 v1(75.72,21.51) ; v1(55.9,58.97) 56.41,59.48 57.1,59.48 57.11,59.49 57.11,59.49 57.41,59.78 57.41,60.45 58.02,61.07 U7.20
  ART03 w0.097: v1(75.72,21.51) 76.21,22 76.21,34.7 71.35,39.56 71.35,52.23 69.17,54.41 69.17,55.29 65.99,58.47 63.11,58.47 62.95,58.63 62.95,59.43 62.79,59.59 62.52,59.59 62.36,59.43 62.36,58.68 62.15,58.47 61.88,58.47 61.72,58.63 61.72,59.43 61.56,59.59 61.24,59.59 61.08,59.43 61.08,58.68 60.87,58.47 60.6,58.47 60.44,58.63 60.44,59.43 60.28,59.59 59.96,59.59 59.8,59.43 59.8,58.68 59.59,58.47 59.32,58.47 59.16,58.63 59.16,59.43 59,59.59 58.68,59.59 58.52,59.43 58.52,58.68 58.31,58.47 56.08,58.47 55.9,58.65 v1(55.9,58.97)
ETH0_TXCTL_M0: length 72.2
  TOP w0.102: v1(56.9,59.97) 56.9,60.58 57.79,61.47 U7.19 ; CN5.23 80.32,19.7 78.99,21.03 77.98,21.03 77.5,21.51 v1(76.73,21.51)
  ART03 w0.097: v1(76.73,21.51) 76.75,21.51 77.21,21.97 77.21,35.21 72.23,40.19 72.23,52.76 70.79,54.2 70.79,55.42 66.52,59.69 66.52,60.68 66.19,61.01 65.83,61.01 65.67,61.17 65.67,61.28 65.51,61.44 65.19,61.44 65.03,61.28 65.03,61.17 64.87,61.01 64.57,61.01 64.41,61.17 64.41,62.6 64.25,62.76 63.96,62.76 63.8,62.6 63.8,61.09 63.61,60.91 63.32,60.91 63.16,61.07 63.16,61.97 63,62.13 62.68,62.13 62.52,61.97 62.52,61.2 62.33,61.01 62.05,61.01 61.84,60.81 61.41,60.81 61.2,61.01 60.77,61.01 60.56,60.81 60.13,60.81 59.92,61.01 59.49,61.01 59.28,60.81 58.85,60.81 58.64,61.01 57.51,61.01 56.9,60.41 v1(56.9,59.97)
ETH0_TXD0_M0: length 72.5
  TOP w0.102: v1(78.26,21.52) 79.06,21.52 80.72,19.86 CN5.25 ; v1(55.9,59.97) 56.47,60.54 56.47,61 56.81,61.34 57.08,61.34 57.6,61.87 U7.18
  ART03 w0.097: v1(78.26,21.52) 77.72,22.06 77.72,35.41 72.69,40.44 72.69,53.04 71.33,54.4 71.33,55.6 66.95,59.97 66.95,60.96 66.55,61.37 66.55,62.18 66.29,62.43 65.86,62.43 65.07,63.22 63.07,63.22 62.1,62.26 59.1,62.26 58.94,62.09 58.94,61.69 58.74,61.49 58.32,61.49 58.2,61.61 58.2,61.84 58.09,61.95 57.93,61.95 57.82,61.84 57.82,61.61 57.7,61.49 55.52,61.49 55.3,61.26 55.3,60.17 55.49,59.97 v1(55.9,59.97)
ETH0_TXD1_M0: length 72.3
  TOP w0.102: v1(55.9,60.97) 55.9,61.15 56.62,61.87 57.08,61.87 57.47,62.27 U7.17 ; v1(76.72,22.51) 77.22,22.01 79.92,22.01 81.12,20.81 CN5.27
  ART03 w0.097: v1(76.72,22.51) 76.72,34.88 71.79,39.81 71.79,52.48 70.24,54.03 70.24,55.13 66.05,59.32 66.05,59.99 65.89,60.15 65.57,60.15 65.41,59.99 65.41,59.16 65.23,58.98 64.93,58.98 64.77,59.14 64.77,59.99 64.61,60.15 64.29,60.15 64.13,59.99 64.13,59.16 63.95,58.98 63.69,58.98 63.53,59.14 63.53,59.99 63.37,60.15 57.61,60.15 57.45,59.99 57.45,59.55 57.29,59.39 56.62,59.39 56.39,59.61 56.39,60.78 56.2,60.97 v1(55.9,60.97)
ETH0_TXD2_M0: length 72.6
  TOP w0.102: U7.16 57.34,62.67 57.03,62.36 56.28,62.36 v1(55.9,61.97) ; v1(78.26,22.52) 80.04,22.52 81.52,21.04 CN5.29
  ART03 w0.097: v1(55.9,61.97) 56.79,61.97 58.22,63.4 62.23,63.4 62.66,63.83 66.46,63.83 66.57,63.72 66.57,63.03 66.68,62.92 66.84,62.92 66.96,63.03 66.96,63.72 67.07,63.83 67.32,63.83 67.49,63.66 67.49,60.1 71.87,55.71 71.87,54.55 73.13,53.29 73.13,40.76 78.26,35.64 v1(78.26,22.52)
ETH0_TXD3_M0: length 72.2
  TOP w0.102: v1(75.72,22.51) 76.2,22.99 80.21,22.99 81.92,21.28 CN5.31 ; U7.15 56.99,63.07 v1(56.9,62.97)
  ART03 w0.097: v1(56.9,62.97) 56.41,62.48 55.32,62.48 54.49,61.65 54.49,58.82 55.47,57.84 65.13,57.84 65.67,57.29 66.43,57.29 68.19,55.54 68.19,54.7 70.92,51.97 70.92,39.27 75.72,34.46 v1(75.72,22.51)
ETH1_MCLK_M0: length 59.8
  TOP w0.102: CN5.18 79.12,12.92 v1(79.22,13.02) ; R73.1 v1(87.17,60.83)
  ART03 w0.097: v1(79.22,13.02) 79.74,13.54 83.24,13.54 86.82,17.12 88.87,17.12 90.3,18.54 90.3,33.73 91.06,34.49 91.06,47.37 88.01,50.42 88.01,54.15 87.63,54.53 87.63,55.19 86.69,56.13 86.69,60.35 v1(87.17,60.83)
ETH1_MDC_M0: length 31.8
  TOP w0.152: U8.13 74.47,63.86 v1(74.31,64.02) ; v1(87.52,51.79) 87.01,51.27 87.01,50.59 86.72,50.3 CN3.56
  ART03 w0.152: v1(87.52,51.79) 87.52,53.68 86.21,54.99 86.21,59.54 84.58,61.16 82.14,61.16 81.23,62.08 77.5,62.08 77.24,62.33 77.24,63.37 76.59,64.02 v1(74.31,64.02)
  BOTTOM w0.152: R72.2 75.62,61.98 74.8,62.79 74.8,63.5 74.31,63.99 v1(74.31,64.02)
ETH1_MDIO_M0: length 31.2
  TOP w0.152: v1(87.52,50.79) 87.52,50.41 87.12,50.01 CN3.58 ; U8.14 74.8,63.47 v1(74.31,62.97)
  ART03 w0.152: v1(87.52,50.79) 87.47,50.79 87,51.26 87,53.39 85.67,54.71 85.67,58.34 84.05,59.97 77.47,59.97 76.68,60.76 76.68,62.94 76.12,63.5 74.84,63.5 v1(74.31,62.97)
  BOTTOM w0.152: R71.2 76.07,60.96 74.31,62.72 v1(74.31,62.97)
ETH1_RSTN: length 32.5
  TOP w0.152: v1(88.52,51.79) 88.04,51.3 88.04,50.42 87.52,49.91 CN3.60
  ART03 w0.152: v1(75.31,67.29) 76.41,66.19 82.04,66.19 82.63,66.78 83.97,66.78 88.49,62.26 88.49,58.8 87.74,58.05 87.74,55.95 88.58,55.11 88.58,51.84 v1(88.52,51.79)
  BOTTOM w0.152: v1(75.31,67.29) 75.31,67.44 73.97,68.78 D60.1
ETH1_RXCLK_M0: length 70.2
  TOP w0.102: R59.2 v1(81.28,56.58) R67.1 ; v1(76.22,13.02) 76.32,12.92 CN5.4
  ART03 w0.097: v1(81.28,56.58) 81.75,56.1 81.75,52.64 82.27,52.12 82.27,50.57 81.94,50.24 81.94,49.33 84,47.27 85.01,47.27 85.32,46.96 85.32,44.93 84.96,44.57 84.96,33.41 85.12,33.25 86.07,33.25 86.23,33.09 86.23,32.77 86.07,32.61 85.12,32.61 84.96,32.45 84.96,32.13 85.12,31.97 86.07,31.97 86.23,31.81 86.23,31.49 86.07,31.33 85.12,31.33 84.96,31.17 84.96,30.85 85.12,30.69 86.07,30.69 86.23,30.53 86.23,30.21 86.07,30.05 85.12,30.05 84.96,29.89 84.96,29.57 85.12,29.41 86.07,29.41 86.23,29.25 86.23,28.93 86.07,28.77 85.12,28.77 84.96,28.61 84.96,28.29 85.12,28.13 85.56,28.13 85.72,27.97 85.72,27.65 85.56,27.49 85.12,27.49 84.96,27.33 84.96,27.01 85.12,26.85 85.56,26.85 85.72,26.69 85.72,26.37 85.56,26.21 85.12,26.21 84.96,26.05 84.96,25.76 85.12,25.6 85.54,25.6 85.7,25.44 85.7,25.12 85.54,24.96 85.12,24.96 84.96,24.8 84.96,24.48 85.12,24.32 85.54,24.32 85.7,24.16 85.7,23.84 85.54,23.68 85.12,23.68 84.96,23.52 84.96,23.2 85.12,23.04 85.54,23.04 85.7,22.88 85.7,22.56 85.54,22.4 85.12,22.4 84.96,22.24 84.96,21.92 85.12,21.76 85.54,21.76 85.7,21.6 85.7,21.28 85.54,21.12 85.12,21.12 84.96,20.96 84.96,19.32 82.25,16.61 78.21,16.61 76.22,14.63 v1(76.22,13.02)
ETH1_RXCTL_M0: length 70.2
  TOP w0.102: R68.1 v1(80.26,56.58) R69.1 ; CN5.6 v1(76.72,11.18)
  ART03 w0.097: v1(76.72,11.18) 76.72,14.37 78.44,16.08 82.37,16.08 85.45,19.15 85.45,19.81 86.23,20.6 86.23,21.44 86.39,21.6 87.27,21.6 87.43,21.76 87.43,22.08 87.27,22.24 86.39,22.24 86.23,22.4 86.23,22.72 86.39,22.88 87.27,22.88 87.43,23.04 87.43,23.36 87.27,23.52 86.39,23.52 86.23,23.68 86.23,24 86.39,24.16 87.27,24.16 87.43,24.32 87.43,24.64 87.27,24.8 86.39,24.8 86.23,24.96 86.23,25.28 86.39,25.44 87.27,25.44 87.43,25.6 87.43,25.92 87.27,26.08 86.39,26.08 86.23,26.24 86.23,26.95 86.37,27.08 86.94,27.08 87.1,27.24 87.1,27.56 86.94,27.72 86.42,27.72 86.23,27.91 86.23,28.19 86.79,28.75 86.79,33.46 86.47,33.78 85.67,33.78 85.45,34.01 85.45,36.53 85.61,36.69 85.92,36.69 86.08,36.85 86.08,37.17 85.92,37.33 85.61,37.33 85.42,37.52 85.42,44.25 85.92,44.75 85.92,47.25 85.34,47.83 84.19,47.83 82.84,49.17 82.84,50.13 82.71,50.27 82.71,52.38 82.25,52.84 82.25,56.34 81.48,57.1 80.78,57.1 v1(80.26,56.58)
ETH1_RXD0_M0: length 71.3
  TOP w0.102: CN5.8 77.12,12.92 v1(77.22,13.02) ; R60.1 v1(79.25,56.58) R57.2
  ART03 w0.097: v1(79.25,56.58) 80.3,57.63 81.56,57.63 83.13,56.06 83.13,50.44 83.44,50.14 83.44,49.31 83.6,49.15 84.42,49.15 85.11,48.46 86.72,48.46 87.33,47.85 87.33,43.99 87.12,43.79 86.18,43.79 85.98,43.59 85.98,40.41 86.15,40.24 86.62,40.24 86.79,40.07 86.79,39.83 86.62,39.66 86.15,39.66 85.98,39.49 85.98,39.25 86.15,39.08 86.62,39.08 86.79,38.91 86.79,38.67 86.62,38.5 86.15,38.5 85.98,38.33 85.98,38.1 86.15,37.94 86.67,37.94 86.84,37.77 86.84,36.6 86,35.76 86,34.62 86.23,34.39 87.82,34.39 88.04,34.17 88.04,33.87 87.88,33.71 87.56,33.71 87.4,33.55 87.4,33.23 87.56,33.07 87.88,33.07 88.04,32.91 88.04,32.59 87.88,32.43 87.56,32.43 87.4,32.27 87.4,31.95 87.56,31.79 87.88,31.79 88.04,31.63 88.04,31.31 87.88,31.15 87.56,31.15 87.4,30.99 87.4,30.67 87.56,30.51 87.88,30.51 88.04,30.35 88.04,30.03 87.88,29.87 87.56,29.87 87.4,29.71 87.4,29.39 87.56,29.23 87.88,29.23 88.04,29.07 88.04,28.75 87.88,28.59 87.51,28.59 87.35,28.43 87.35,28.11 87.51,27.95 87.88,27.95 88.04,27.79 88.04,21.54 86.23,19.74 86.23,19.23 82.55,15.54 78.64,15.54 77.22,14.13 v1(77.22,13.02)
ETH1_RXD1_M0: length 70.6
  TOP w0.102: R61.1 v1(78.23,56.58) R58.2 ; CN5.10 77.52,11.38 v1(77.72,11.18)
  ART03 w0.097: v1(77.72,11.18) 77.72,13.89 78.88,15.05 82.69,15.05 86.59,18.95 87.01,18.95 87.2,19.14 87.2,19.76 88.6,21.16 88.6,34.37 87.91,35.05 87.4,35.05 87.2,35.26 87.2,36.04 87.45,36.3 88.33,36.3 88.49,36.46 88.49,36.79 88.33,36.95 87.61,36.95 87.45,37.11 87.45,37.43 87.61,37.59 88.33,37.59 88.44,37.7 88.44,38.25 88.29,38.4 87.66,38.4 87.43,38.63 87.43,40.73 87.26,40.9 86.76,40.9 86.59,41.07 86.59,41.31 86.76,41.48 87.26,41.48 87.43,41.65 87.43,42.37 87.68,42.62 88.39,42.62 88.54,42.77 88.54,47.55 87.17,48.92 85.83,48.92 84.11,50.63 84.11,53.4 83.72,53.8 83.72,56.11 81.64,58.19 79.84,58.19 v1(78.23,56.58)
ETH1_RXD2_M0: length 71.2
  TOP w0.102: v1(78.22,13.02) 77.92,12.72 CN5.12 ; R63.1 v1(77.22,56.58) R65.1
  ART03 w0.097: v1(78.22,13.02) 78.22,13.63 79.15,14.55 82.85,14.55 86.39,18.08 87.88,18.08 88.29,18.49 88.29,19.81 89.15,20.68 89.15,34.65 88.6,35.2 88.6,35.71 89.08,36.2 89.08,38.83 88.91,39 88.13,39 87.96,39.17 87.96,39.41 88.13,39.58 88.91,39.58 89.08,39.75 89.08,39.99 88.91,40.16 88.13,40.16 87.96,40.33 87.96,40.57 88.13,40.74 88.91,40.74 89.08,40.91 89.08,41.15 88.91,41.32 88.13,41.32 87.96,41.49 87.96,41.73 88.13,41.9 88.91,41.9 89.08,42.07 89.08,47.78 87.38,49.48 86.11,49.48 85.04,50.55 85.04,53.42 84.56,53.89 84.56,56.21 84.15,56.62 83.85,56.62 81.66,58.8 79.44,58.8 v1(77.22,56.58)
ETH1_RXD3_M0: length 69.8
  TOP w0.102: R66.1 v1(76.2,56.58) R64.1 ; v1(78.72,11.18) 78.5,11.18 78.32,11.35 CN5.14
  ART03 w0.097: v1(76.2,56.58) 78.93,59.31 81.89,59.31 83.39,57.81 84.35,57.81 85.06,57.1 85.06,54.33 86.11,53.28 86.11,50.37 86.52,49.96 87.66,49.96 89.99,47.62 89.99,44.91 89.74,44.65 89.74,20.52 89.15,19.94 89.15,18.69 88.06,17.6 86.61,17.6 83.04,14.03 79.33,14.03 78.72,13.42 v1(78.72,11.18)
ETH1_TXCLK_M0: length 62.7
  TOP w0.102: v1(74.31,58.97) 74.82,59.48 75.52,59.48 75.52,59.49 75.52,59.49 75.82,59.78 75.82,60.45 76.43,61.07 U8.20 ; CN5.3 76.32,17.1 75.72,17.7 v1(75.72,18.51)
  ART03 w0.097: v1(75.72,18.51) 76.3,17.92 79.95,17.92 83.03,21.01 83.03,42.82 82.25,43.61 79.63,43.61 79.35,43.89 79.35,44.73 79.58,44.96 80.7,44.96 80.98,45.24 80.98,47.68 80.71,47.94 80.71,49.85 80.06,50.5 80.06,52.02 78.94,53.14 78.94,54.05 77.72,55.27 76.02,55.27 75.17,56.13 75.17,57.7 74.31,58.56 v1(74.31,58.97)
ETH1_TXCTL_M0: length 63.3
  TOP w0.102: U8.19 76.2,61.47 75.31,60.58 v1(75.31,59.97) ; v1(75.72,19.51) 76.23,19 76.23,17.86 76.72,17.36 CN5.5
  ART03 w0.097: v1(75.72,19.51) 75.23,19.02 75.23,18.34 76.14,17.43 80.22,17.43 83.59,20.8 83.59,43.1 81.41,45.29 81.41,46.71 81.76,47.07 81.76,47.52 81.15,48.13 81.15,50.01 80.52,50.65 80.52,52.22 79.39,53.35 79.39,54.24 77.75,55.88 76.18,55.88 75.66,56.41 75.66,58.05 74.9,58.8 74.9,59.56 v1(75.31,59.97)
ETH1_TXD0_M0: length 62.2
  TOP w0.102: v1(78.32,19.15) CN5.13 ; v1(74.31,59.97) 74.88,60.54 74.88,61 75.22,61.34 75.49,61.34 76.01,61.87 U8.18
  ART03 w0.097: v1(74.31,59.97) 74.63,59.97 74.86,60.2 74.86,61.23 74.63,61.46 73.36,61.46 73.17,61.27 73.17,58.18 74.24,57.11 74.24,55.43 75.97,53.7 75.97,50.65 75.39,50.06 75.39,44.32 76.23,43.48 78.21,43.48 79.58,42.11 81.48,42.11 81.88,41.72 81.88,21.5 79.88,19.51 78.68,19.51 v1(78.32,19.15)
ETH1_TXD1_M0: length 62.6
  TOP w0.102: v1(77.72,18.51) 77.92,18.31 CN5.11 ; v1(74.31,60.97) 74.31,61.15 75.03,61.87 75.49,61.87 75.88,62.27 U8.17
  ART03 w0.097: v1(74.31,60.97) 73.66,60.32 73.66,58.42 74.68,57.4 74.68,55.75 75.77,54.66 77.4,54.66 77.72,54.34 77.72,52.37 78.03,52.07 78.03,50.62 77.67,50.27 76.2,50.27 75.87,49.94 75.87,44.65 76.43,44.09 78.33,44.09 79.73,42.7 82.12,42.7 82.44,42.37 82.44,21.25 80.19,19 78.84,19 78.35,18.51 v1(77.72,18.51)
ETH1_TXD2_M0: length 62.2
  TOP w0.102: v1(74.31,61.97) 74.69,62.36 75.44,62.36 75.75,62.67 U8.16 ; v1(76.72,19.51) 77.23,19 77.23,18.15 77.52,17.85 CN5.9
  ART03 w0.097: v1(76.72,19.51) 77.23,20.02 79.63,20.02 81.41,21.79 81.41,41.35 81.23,41.53 80.9,41.53 80.73,41.36 80.73,40.94 80.56,40.77 80.32,40.77 80.16,40.94 80.16,41.36 79.99,41.53 79.25,41.53 77.73,43.05 75.8,43.05 74.96,43.89 74.96,54.08 73.77,55.26 73.77,56.81 72.68,57.9 72.68,61.65 73,61.97 v1(74.31,61.97)
ETH1_TXD3_M0: length 62.4
  TOP w0.102: v1(76.72,18.51) 76.72,17.99 77.12,17.59 CN5.7 ; v1(75.31,62.97) 75.4,63.07 U8.15
  ART03 w0.097: v1(75.31,62.97) 74.82,62.48 73.13,62.48 72.97,62.64 72.97,62.98 72.81,63.14 72.35,63.14 72.19,62.98 72.19,57.7 73.33,56.56 73.33,55.07 74.52,53.87 74.52,43.53 75.43,42.62 77.29,42.62 80.77,39.14 80.77,21.77 79.51,20.51 76.55,20.51 76.23,20.19 76.23,18.83 76.55,18.51 v1(76.72,18.51)
FAN_CTRL: length 81.3
  TOP w0.152: R13.1 v1(54.23,54.86) ; v1(87.72,11.18) 87.92,11.38 CN5.62
  ART03 w0.152: v1(50.5,22.5) 50.27,22.73 50.27,48.29 52.1,50.11 52.1,52.73 v1(54.23,54.86)
  BOTTOM w0.152: v1(50.5,22.5) 50.83,22.17 63.47,22.17 66.34,19.3 73.53,19.3 74.24,20.02 76.38,20.02 76.76,20.4 79.78,20.4 81.03,19.15 81.03,16.69 82.35,15.37 83.97,15.37 85.42,13.92 87.07,13.92 87.72,13.27 v1(87.72,11.18)
FUSB302_INT: length 51.6
  TOP w0.152: CN2.39 59.92,44.86 59.44,44.38 59.44,42.93 59.14,42.63 56.65,42.63 55.88,41.86 40.54,41.86 v1(40.17,42.23)
  ART03 w0.152: v1(40.17,42.23) 38.25,44.15 38.25,52.48 40.28,54.51 40.28,61.32 40.97,62 v1(40.97,64.41)
  BOTTOM w0.152: U11.5 39.19,64.64 39.42,64.41 v1(40.97,64.41) 41.69,64.41 41.92,64.64 R109.2
HDMI_5V: length 5.7
  BOTTOM w0.508: J33.18 99.44,71.5 D48.1
HDMI_TX_CEC_M0: length 15.2
  TOP w0.152: CN3.46 84.72,49.52 84.81,49.61 84.81,50.22 84.68,50.34 84.68,51.62 v1(84.52,51.79)
  BOTTOM w0.152: R152.1 87.66,62.09 87.66,59.08 85.64,57.06 85.64,54.7 84.52,53.59 v1(84.52,51.79)
HDMI_TX_CEC_PORT: length 18.4
  BOTTOM w0.152: Q10.3 86.36,68.63 87.35,69.62 91.97,69.62 93.37,71.02 93.37,73.69 94.13,74.45 95.8,74.45 96.16,74.81 D43.2 98.19,74.93 J33.13
HDMI_TX_D0N: length 87.7
  TOP w0.084: v1(96.23,60.4) 95.99,60.4 arc(95.94,60.4) 95.9,60.43 95.89,60.44 arc(95.87,60.48) 95.86,60.53 95.86,61.92 arc(95.89,62.07) 95.97,62.2 C221.1 ; v1(63.92,43.11) 63.92,43.3 arc(63.89,43.46) 63.8,43.59 63.61,43.79 arc(63.49,43.96) 63.45,44.16 63.45,44.18 arc(63.49,44.38) 63.61,44.56 63.91,44.86 arc(63.99,44.99) 64.02,45.13 64.02,45.25 arc(64.01,45.31) 63.98,45.36 63.97,45.37 arc(63.93,45.42) 63.92,45.48 CN2.59
  BOTTOM w0.084: v1(96.23,60.4) 95.97,60.4 arc(95.84,60.45) 95.78,60.58 95.78,60.95 arc(95.83,61.21) 95.98,61.44 96.21,61.66 arc(96.42,61.8) 96.67,61.85 105.07,61.85 arc(105.64,61.74) 106.12,61.42 107.82,59.72 arc(108.14,59.24) 108.25,58.67 108.25,45.9 arc(108.14,45.33) 107.82,44.86 99.69,36.72 arc(99.21,36.4) 98.65,36.29 75.34,36.29 arc(74.92,36.38) 74.56,36.61 74.32,36.86 arc(74.1,37.01) 73.83,37.06 67.8,37.06 arc(67.23,37.17) 66.75,37.49 64.59,39.65 arc(64.42,39.9) 64.36,40.2 64.36,40.46 arc(64.39,40.51) 64.44,40.54 arc(64.49,40.56) 64.52,40.61 64.52,40.79 arc(64.49,40.85) 64.44,40.87 arc(64.39,40.89) 64.36,40.95 64.36,41.13 arc(64.39,41.18) 64.44,41.21 arc(64.49,41.23) 64.52,41.28 64.52,41.46 arc(64.49,41.52) 64.44,41.54 arc(64.39,41.56) 64.36,41.62 64.36,41.69 arc(64.34,41.82) 64.27,41.93 63.79,42.4 arc(63.69,42.55) 63.65,42.74 63.65,42.95 arc(63.7,43.07) 63.81,43.11 v1(63.92,43.11)
HDMI_TX_D0N_PORT: length 16.7
  TOP w0.084: J33.9 98.59,77 arc(98.5,77.23) 98.27,77.32 97.87,77.32 97.64,77.09 arc(97.56,76.97) 97.54,76.83 97.54,76.73 arc(97.56,76.68) 97.61,76.66 arc(97.67,76.64) 97.69,76.58 97.69,76.4 arc(97.67,76.34) 97.61,76.32 arc(97.56,76.3) 97.54,76.25 97.54,76.06 arc(97.56,76.01) 97.61,75.99 arc(97.67,75.96) 97.69,75.91 97.69,75.73 arc(97.67,75.67) 97.61,75.65 arc(97.56,75.63) 97.54,75.58 97.54,68.66 arc(97.49,68.44) 97.37,68.26 95.91,66.8 arc(95.82,66.67) 95.79,66.52 95.79,66.43 arc(95.82,66.31) 95.89,66.21 95.9,66.2 arc(95.97,66.1) 95.99,65.97 D50.2 95.89,65.69 arc(95.83,65.59) 95.8,65.47 95.8,65.15 arc(95.83,65) 95.92,64.87 R233.1 95.92,64.16 arc(95.87,64.09) 95.85,64.01 95.85,63.99 arc(95.87,63.91) 95.92,63.84 C221.2
HDMI_TX_D0P: length 88
  TOP w0.084: C220.1 95.54,62.2 arc(95.63,62.07) 95.66,61.92 95.66,60.88 arc(95.66,60.85) 95.65,60.82 arc(95.61,60.7) 95.54,60.6 v1(95.34,60.4) ; v1(63.92,44.11) 63.74,44.29 arc(63.72,44.35) 63.74,44.41 64.05,44.72 arc(64.18,44.91) 64.22,45.13 64.22,45.25 arc(64.23,45.31) 64.27,45.36 64.28,45.37 arc(64.31,45.42) 64.32,45.48 CN2.61
  BOTTOM w0.084: v1(95.34,60.4) 95.47,60.52 arc(95.55,60.65) 95.58,60.8 95.58,60.95 arc(95.65,61.29) 95.84,61.58 96.07,61.8 arc(96.34,61.99) 96.67,62.05 105.07,62.05 arc(105.71,61.92) 106.26,61.56 107.96,59.86 arc(108.33,59.31) 108.45,58.67 108.45,45.9 arc(108.33,45.26) 107.96,44.71 99.83,36.58 arc(99.29,36.22) 98.65,36.09 75.34,36.09 arc(74.84,36.19) 74.42,36.47 74.18,36.72 arc(74.02,36.82) 73.83,36.86 67.8,36.86 arc(67.15,36.99) 66.61,37.35 64.45,39.51 arc(64.24,39.83) 64.17,40.2 64.17,41.69 arc(64.16,41.74) 64.13,41.79 63.62,42.3 arc(63.49,42.48) 63.45,42.7 63.45,43.14 arc(63.48,43.29) 63.57,43.43 63.81,43.67 arc(63.89,43.79) 63.92,43.94 v1(63.92,44.11)
HDMI_TX_D0P_PORT: length 16.4
  TOP w0.084: C220.2 95.59,63.83 arc(95.64,63.91) 95.66,63.99 95.66,64.01 arc(95.64,64.09) 95.59,64.17 R234.1 95.43,64.7 arc(95.56,64.9) 95.61,65.13 95.61,65.44 arc(95.58,65.57) 95.51,65.68 D49.2 95.4,65.97 arc(95.42,66.1) 95.49,66.2 95.5,66.21 arc(95.57,66.31) 95.6,66.43 95.6,66.52 arc(95.64,66.75) 95.77,66.94 97.23,68.4 arc(97.31,68.52) 97.34,68.66 97.34,76.83 arc(97.38,77.05) 97.5,77.23 97.79,77.52 97.96,77.52 arc(98.1,77.55) 98.22,77.63 J33.7
HDMI_TX_D1N: length 79
  TOP w0.084: C219.1 105.57,62.2 arc(105.66,62.07) 105.69,61.92 105.69,60.62 arc(105.68,60.54) 105.63,60.47 105.62,60.45 arc(105.55,60.41) 105.47,60.4 v1(105.37,60.4) ; CN2.63 64.72,45.48 arc(64.73,45.42) 64.77,45.37 64.78,45.36 arc(64.81,45.31) 64.82,45.25 64.82,44.92 arc(64.78,44.68) 64.64,44.47 64.55,44.38 arc(64.47,44.26) 64.44,44.12 64.44,44.1 arc(64.47,43.95) 64.55,43.83 64.81,43.58 arc(64.89,43.45) 64.92,43.29 v1(64.92,43.11)
  BOTTOM w0.084: v1(64.92,43.11) 64.8,43.11 arc(64.71,43.08) 64.67,42.99 64.67,42.75 arc(64.71,42.54) 64.82,42.37 65.24,41.96 arc(65.3,41.85) 65.33,41.73 65.33,41.65 arc(65.35,41.61) 65.39,41.59 arc(65.44,41.57) 65.46,41.53 65.46,41.32 arc(65.44,41.27) 65.39,41.26 arc(65.35,41.24) 65.33,41.19 65.33,40.98 arc(65.35,40.94) 65.39,40.92 arc(65.44,40.9) 65.46,40.86 65.46,40.65 arc(65.44,40.6) 65.39,40.58 arc(65.35,40.57) 65.33,40.52 65.33,40.4 arc(65.36,40.25) 65.45,40.12 67.16,38.41 arc(67.64,38.09) 68.2,37.97 73.84,37.97 arc(74.45,37.85) 74.96,37.51 75.03,37.44 arc(75.48,37.14) 76.02,37.03 98.13,37.03 arc(98.69,37.15) 99.17,37.47 106.63,44.93 arc(106.95,45.41) 107.07,45.97 107.07,55.98 arc(106.63,57.03) 105.59,57.46 105.28,57.46 arc(104.88,57.87) 105.28,58.27 106.86,58.27 arc(107,58.34) 107.07,58.48 107.07,58.69 arc(107.01,58.84) 106.86,58.9 104.24,58.9 arc(103.84,59.3) 104.24,59.71 105.58,59.71 arc(105.73,59.77) 105.79,59.92 105.79,60.27 arc(105.76,60.36) 105.67,60.4 v1(105.37,60.4)
HDMI_TX_D1N_PORT: length 25.1
  TOP w0.084: C219.2 105.62,63.83 arc(105.67,63.91) 105.69,63.99 105.69,64.01 arc(105.67,64.09) 105.62,64.17 R231.1 105.64,64.88 arc(105.72,65.01) 105.76,65.16 105.76,65.46 arc(105.73,65.58) 105.66,65.68 D56.2 105.56,65.97 arc(105.58,66.1) 105.65,66.2 105.66,66.21 arc(105.73,66.31) 105.76,66.43 105.76,78.13 arc(105.73,78.26) 105.66,78.36 105.06,78.96 arc(104.95,79.04) 104.82,79.06 103.5,79.06 arc(103.35,79) 103.29,78.85 103.29,78.44 arc(102.88,78.03) 102.48,78.44 102.48,78.85 arc(102.27,79.06) 102.06,78.85 102.06,78.44 arc(101.65,78.03) 101.24,78.44 101.24,78.85 arc(101.18,79) 101.03,79.06 100.24,79.06 arc(100.08,79.03) 99.95,78.94 J33.6
HDMI_TX_D1P: length 78.7
  TOP w0.084: v1(64.92,44.11) 64.92,44.39 arc(64.93,44.45) 64.97,44.49 64.98,44.51 arc(65.01,44.55) 65.02,44.61 65.02,45.25 arc(65.03,45.31) 65.07,45.36 65.08,45.37 arc(65.11,45.42) 65.12,45.48 CN2.65 ; v1(106.26,60.4) 106.2,60.4 arc(106.16,60.4) 106.12,60.43 106.01,60.54 arc(105.92,60.67) 105.89,60.82 105.89,61.92 arc(105.92,62.07) 106.01,62.2 C218.1
  BOTTOM w0.084: v1(64.92,44.11) 64.92,43.93 arc(64.89,43.78) 64.81,43.65 64.58,43.42 arc(64.5,43.3) 64.47,43.16 64.47,42.75 arc(64.53,42.47) 64.68,42.23 65.1,41.82 arc(65.12,41.78) 65.13,41.73 65.13,40.4 arc(65.18,40.17) 65.31,39.98 67.02,38.27 arc(67.56,37.9) 68.2,37.77 73.84,37.77 arc(74.37,37.67) 74.82,37.37 74.89,37.3 arc(75.41,36.96) 76.02,36.84 98.13,36.84 arc(98.77,36.96) 99.31,37.33 106.77,44.79 arc(107.14,45.33) 107.26,45.97 107.26,55.98 arc(106.77,57.17) 105.59,57.66 105.28,57.66 arc(105.07,57.87) 105.28,58.08 106.86,58.08 arc(107.14,58.2) 107.26,58.48 107.26,58.69 arc(107.15,58.98) 106.86,59.1 104.24,59.1 arc(104.03,59.3) 104.24,59.51 105.58,59.51 arc(105.87,59.63) 105.99,59.92 105.99,59.94 arc(106.02,60.11) 106.12,60.25 v1(106.26,60.4)
HDMI_TX_D1P_PORT: length 25.4
  TOP w0.084: C218.2 105.95,63.84 arc(105.9,63.91) 105.89,63.99 105.89,64.01 arc(105.9,64.09) 105.95,64.16 R232.1 106.07,64.75 arc(105.98,64.88) 105.95,65.04 105.95,65.46 arc(105.98,65.58) 106.05,65.68 D55.2 106.15,65.97 arc(106.13,66.1) 106.06,66.2 106.05,66.21 arc(105.98,66.31) 105.95,66.43 105.95,78.13 arc(105.91,78.33) 105.8,78.5 105.2,79.1 arc(105.03,79.22) 104.82,79.26 103.5,79.26 arc(103.21,79.14) 103.09,78.85 103.09,78.44 arc(102.88,78.23) 102.67,78.44 102.67,78.85 arc(102.27,79.26) 101.86,78.85 101.86,78.44 arc(101.65,78.23) 101.44,78.44 101.44,78.85 arc(101.32,79.14) 101.03,79.26 100.24,79.26 arc(100.08,79.29) 99.95,79.38 J33.4
HDMI_TX_D2N: length 82
  TOP w0.084: v1(65.92,43.11) 65.92,43.3 arc(65.89,43.46) 65.8,43.6 65.58,43.82 arc(65.49,43.95) 65.46,44.11 65.46,44.19 arc(65.48,44.29) 65.53,44.38 65.55,44.39 arc(65.6,44.47) 65.62,44.58 65.62,45.25 arc(65.61,45.31) 65.58,45.36 65.57,45.37 arc(65.53,45.42) 65.52,45.48 CN2.67 ; v1(92.11,59.43) 92.09,59.41 arc(92.01,59.38) 91.92,59.41 91.89,59.44 arc(91.82,59.55) 91.79,59.68 91.79,62.05 arc(91.8,62.08) 91.82,62.11 C217.1
  BOTTOM w0.084: v1(65.92,43.11) 65.79,43.11 arc(65.68,43.07) 65.63,42.96 65.63,42.8 arc(65.66,42.68) 65.73,42.57 66.2,42.1 arc(66.27,42) 66.29,41.87 66.29,41.8 arc(66.32,41.74) 66.37,41.72 arc(66.42,41.7) 66.45,41.64 66.45,41.46 arc(66.42,41.41) 66.37,41.38 arc(66.32,41.36) 66.29,41.31 66.29,41.12 arc(66.32,41.07) 66.37,41.05 arc(66.42,41.03) 66.45,40.97 66.45,40.79 arc(66.42,40.74) 66.37,40.71 arc(66.32,40.69) 66.29,40.64 66.29,40.55 arc(66.32,40.42) 66.39,40.31 66.46,40.24 arc(66.52,40.22) 66.57,40.24 arc(66.63,40.27) 66.69,40.24 66.81,40.12 arc(66.84,40.06) 66.81,40.01 arc(66.79,39.95) 66.81,39.89 66.94,39.77 arc(66.99,39.75) 67.05,39.77 arc(67.11,39.79) 67.16,39.77 67.29,39.65 arc(67.31,39.59) 67.29,39.53 arc(67.26,39.48) 67.29,39.42 67.52,39.19 arc(67.82,38.98) 68.18,38.91 74.21,38.91 arc(74.85,38.79) 75.4,38.42 75.59,38.23 arc(76.07,37.91) 76.63,37.8 97.28,37.8 arc(97.85,37.91) 98.32,38.23 104.95,44.86 arc(105.27,45.33) 105.38,45.9 105.38,53.87 arc(105.27,54.44) 104.95,54.92 104.45,55.41 arc(104.09,55.96) 103.96,56.6 103.96,56.99 arc(103.85,57.56) 103.53,58.04 103.39,58.18 arc(103.02,58.73) 102.9,59.37 102.9,59.69 arc(102.69,60.19) 102.18,60.4 99.06,60.4 arc(98.5,60.29) 98.02,59.97 97.91,59.86 arc(97.36,59.49) 96.72,59.36 93.68,59.36 arc(93.53,59.39) 93.4,59.48 93,59.88 arc(92.67,60.1) 92.29,60.18 91.97,60.18 arc(91.86,60.16) 91.77,60.09 91.75,60.08 arc(91.69,59.98) 91.67,59.87 91.67,59.61 arc(91.68,59.55) 91.72,59.49 91.73,59.48 arc(91.78,59.44) 91.85,59.43 v1(92.11,59.43)
